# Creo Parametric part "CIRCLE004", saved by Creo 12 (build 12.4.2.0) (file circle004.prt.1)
Units: Custom; MM, KILOGRAM, SECS

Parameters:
  PTC_WM_ITERATION = "0"
  PTC_WM_VERSION = "-.0"
  PTC_WM_LIFECYCLE_STATE = "In Work"
  PTC_WM_LIFECYCLE = "MO_CADDocument"
  PTC_WM_CREATED_BY = "Maximilian Roepper (Z0017RMS: MO)"
  PTC_WM_CREATED_ON = "18-Sep-26 11:36:42 AM"
  PTC_WM_MODIFIED_BY = "Maximilian Roepper (Z0017RMS: MO)"
  PTC_WM_MODIFIED_ON = "18-Sep-26 11:36:46 AM"
  PDMLINKNUMBER = "PDM000071454755"
  PTC_WM_NAME = "circle004.prt"
  PTC_WM_NUMBER = "PDM000071454755"

Other parameters: WEIGHT, WEIGHT_FACTOR, WEIGHT_ADD, _MASS_TEMP, _DIFF_TEMP, MC_ERRORS, SUPPLIER

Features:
  1. coordinate system
  2. datum plane "PRT_YZ"
  3. datum plane "PRT_XY"
  4. datum plane "PRT_XZ"
  5. coordinate system
  6. datum axis
  7. datum axis
  8. datum axis
  9. coordinate system
  10. imported feature
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
Other named items: PRT, SIEMENS_MO, DRW_VIEW_ORG, PRT_X, PRT_Y, PRT_Z, CS0, ROUGH_GROB

Layers: 00_STD_CSYS-KSYS, 01_STD_PLANES-EBENEN, 02_STD_AXES-ACHSEN, 03_STD_CSYS-KSYS, 24_IMPORT_FEAT-IMPORT_KE

Surfaces: 2 cylinder, 2 plane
